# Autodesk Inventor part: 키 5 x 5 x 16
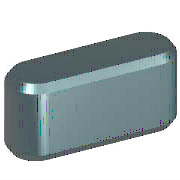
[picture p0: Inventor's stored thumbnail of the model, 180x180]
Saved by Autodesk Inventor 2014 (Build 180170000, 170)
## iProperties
IsCustomPart: 1
Created: 2012-02
Part Number: 키 5 x 5 x 16
Material: 강철, 연강
Description: 키 및 해당 키홈
Document SubType Name: Modeling
Standard: KS B 1311
Designer: mduedu
Standards Organization: KS
Language: ko-KR
Size Designation: 5 x 5 x 16
Categories: <MemberInstance><Categories><Category DisplayName="샤프트 부품" InternalName="7f7aeb1f-a693-4053-b835-cee3144e0d98" Mnemonic="SHFT"><Category DisplayName="키" Interna
Density: 1 g/cm^3
Appearance: Steel
Author: mduedu
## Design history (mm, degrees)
sketch "스케치1"
  geometry: L1 (2.5, 2.5)-(13.5, 2.5); L2 (13.5, -2.5)-(2.5, -2.5); L3 (0, 9.4)-(0, -7.4) reference; L4 (-5, 0)-(30, 0) reference; L5 (16, 0)-(16, 7); A1 r 2.5 centre (2.5, 0) between (2.5, 2.5) and (2.5, -2.5); A2 r 2.5 centre (13.5, 0) between (13.5, -2.5) and (13.5, 2.5)
  constraints: 6 end point, 5 point on circle, 4 tangent, 3 point on line, 2 centre point, 1 horizontal, 1 parallel, 1 perpendicular
  dimensions: "d0" = 2.5 radius of A1 (= 0.5 x PB); "d13" = 2.5 radius of A2 (= 0.5 x PB); "d14" = 16 distance between parallel lines of L5 L3 (= NLG)
extrude "본체1" new body sketch "스케치1" taper "d3" = 0 deg; stored distance "d4" = 10
workplane "Work Plane3"
body "Solid1"
workplane "Work Plane1"
workplane "Work Plane2"
chamfer "모따기1" distance "d8" = 0.4 (= PHH); stored, may be unused: second distance "d9" = 0.4 (= PHH), angle "d15" = 45 deg
other parameters: "d1" = -3 (= -PNT), "d2" = 2 (= PH - PNT), "NLG" = 16 [user parameter; used in 3 equation terms], "PB" = 5 [user parameter; used in 2 equation terms], "PNT" = 3 [user parameter; used in 2 equation terms], "PH" = 5 [user parameter; used in 1 equation term], "PHH" = 0.4 [user parameter; used in 2 equation terms], "d10" = 0, "d16" = 0, "d17" = 0, "d18" = 0, "WDMIN" = 12 [user parameter], "PLB2" = 16 (= NLG) [user parameter], "WDMAX" = 17 [user parameter], "PLB1" = 16 (= NLG) [user parameter], "RR" = 0.16 [user parameter], "PUEB" = 2.3 [user parameter]
